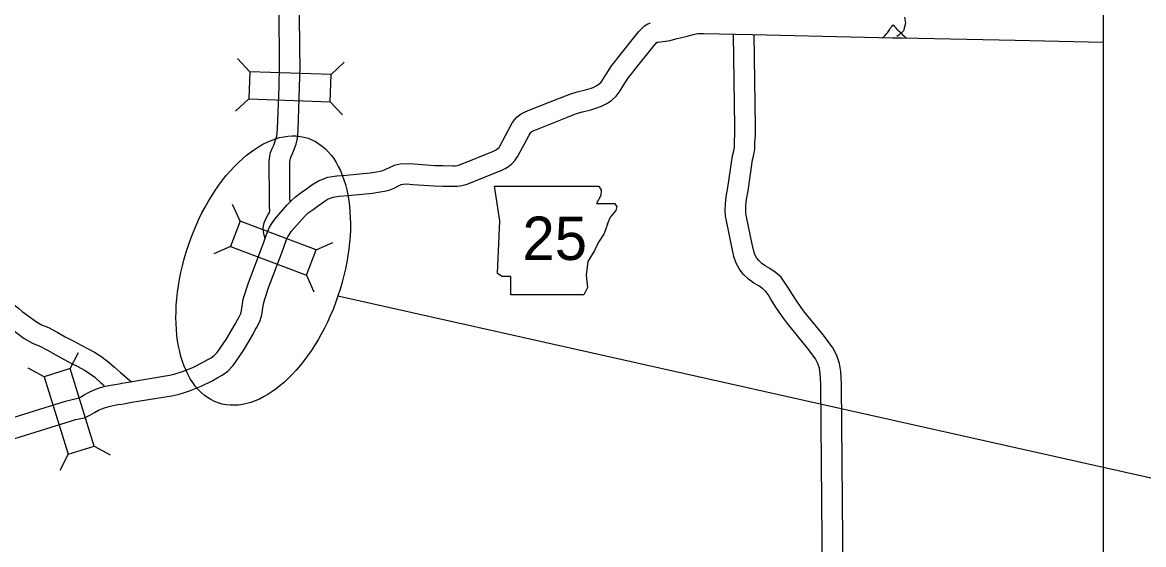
# Model space of a CAD drawing. Extents: x 1212896 to 1368412, y 378476 to 478763.
# Drawn here: x 1230517 to 1246876, y 456675 to 464301 of the extents above; entities that cross this region are included whole.
import ezdxf

# ---------------------------------------------------------------- set-up
doc = ezdxf.new("R2010")
doc.units = 0
for name, color, linetype in [('1', 7, 'Continuous'), ('Level 10', 7, 'Continuous'), ('Level 20', 7, 'Continuous'), ('Level 21', 7, 'Continuous'), ('R_Draft', 7, 'Continuous')]:
    doc.layers.add(name, color=color, linetype=linetype)

msp = doc.modelspace()

# ---------------------------------------------------------------- linework, layer by layer
at = {"layer": '1'}
msp.add_line((1235121, 460306), (1248775, 457249), dxfattribs=at)
msp.add_lwpolyline([(1215273, 477661), (1246287, 477661), (1246287, 445613), (1215273, 445613)], close=True, dxfattribs=at)
at = {"layer": 'Level 10'}
for points in [[(1234061, 461147), (1234043, 461192), (1234033, 461240), (1234029, 461301), (1234044, 461374), (1234075, 461443), (1234103, 461496), (1234124, 461524), (1234126, 461548), (1234123, 461614), (1234124, 461675), (1234121, 461705), (1234120, 461767), (1234118, 462222), (1234119, 462281), (1234126, 462342), (1234139, 462402), (1234161, 462458), (1234184, 462510), (1234207, 462567), (1234221, 462608), (1234229, 462641), (1234236, 462684), (1234239, 462747), (1234261, 463359), (1234269, 463669), (1234267, 463884), (1234256, 464690)], [(1234425, 461688), (1234425, 461691), (1234421, 461725), (1234420, 461769), (1234418, 462221), (1234419, 462261), (1234422, 462292), (1234427, 462315), (1234439, 462344), (1234461, 462395), (1234487, 462460), (1234509, 462521), (1234524, 462584), (1234535, 462654), (1234539, 462733), (1234560, 463349), (1234569, 463667), (1234567, 463887), (1234559, 464463)], [(1230081, 458438), (1231146, 458769), (1231221, 458791), (1231283, 458804), (1231328, 458813), (1231363, 458830), (1231418, 458862), (1231489, 458903), (1231562, 458937), (1231625, 458960), (1231705, 458982), (1231777, 458999), (1231863, 459015), (1231926, 459024), (1231967, 459030), (1232031, 459043), (1232664, 459148), (1232729, 459163), (1232777, 459177), (1232853, 459203), (1232918, 459227), (1233001, 459262), (1233145, 459334), (1233224, 459377), (1233270, 459402), (1233317, 459435), (1233358, 459479), (1233489, 459671), (1233620, 459895), (1233654, 459958), (1233680, 460000), (1233703, 460048), (1233714, 460092), (1233740, 460257), (1233766, 460346), (1233788, 460412), (1233815, 460499), (1234026, 461053), (1234093, 461240), (1234124, 461312), (1234156, 461362), (1234199, 461428), (1234374, 461630), (1234436, 461697), (1234500, 461753), (1234586, 461815), (1234662, 461868), (1234740, 461927), (1234835, 461989), (1234975, 462039), (1235104, 462059), (1235241, 462072), (1235589, 462105), (1235684, 462120), (1235735, 462130), (1235778, 462140), (1235820, 462156), (1235873, 462184), (1235944, 462215), (1236027, 462237), (1236121, 462242), (1236235, 462234), (1236537, 462213), (1236657, 462211), (1236794, 462207), (1236832, 462208), (1236867, 462213), (1236911, 462225), (1237393, 462420), (1237420, 462433), (1237436, 462443), (1237454, 462457), (1237471, 462475), (1237489, 462502), (1237645, 462794), (1237669, 462840), (1237701, 462883), (1237737, 462923), (1237793, 462963), (1237854, 462994), (1237922, 463022), (1238355, 463193), (1238441, 463230), (1238504, 463254), (1238613, 463286), (1238734, 463314), (1238802, 463335), (1238846, 463351), (1238889, 463373), (1238929, 463401), (1238960, 463426), (1238988, 463467), (1239031, 463533), (1239114, 463667), (1239159, 463725), (1239206, 463782), (1239510, 464166), (1239555, 464210), (1239594, 464251), (1239642, 464280), (1239680, 464296)], [(1243389, 464377), (1243402, 464289), (1243372, 464179), (1243311, 464117), (1243276, 464095)], [(1239758, 464008), (1239792, 464013), (1239968, 464038), (1240016, 464052), (1240072, 464067), (1240201, 464097), (1240306, 464122), (1240373, 464137), (1240456, 464137), (1240919, 464130), (1241172, 464125), (1243211, 464077), (1243354, 464076), (1245001, 464039), (1246287, 464010)], [(1242193, 456181), (1242168, 459007), (1242163, 459106), (1242159, 459169), (1242146, 459251), (1242124, 459317), (1242087, 459389), (1242034, 459461), (1241971, 459545), (1241679, 459905), (1241623, 459980), (1241566, 460065), (1241503, 460159), (1241438, 460259), (1241398, 460328), (1241365, 460373), (1241319, 460412), (1241261, 460452), (1241189, 460493), (1241110, 460551), (1241034, 460625), (1240982, 460697), (1240931, 460784), (1240898, 460880), (1240871, 461000), (1240790, 461403), (1240776, 461473), (1240773, 461558), (1240776, 461646), (1240786, 461755), (1240811, 461892), (1240877, 462351), (1240897, 462425), (1240905, 462479), (1240906, 462564), (1240913, 462663), (1240914, 462776), (1240894, 464126), (1240891, 464128)], [(1243067, 464078), (1243075, 464083), (1243087, 464092), (1243095, 464101), (1243104, 464109), (1243116, 464122), (1243131, 464138), (1243138, 464149), (1243151, 464164), (1243160, 464179), (1243168, 464190), (1243176, 464202), (1243186, 464220), (1243194, 464232), (1243201, 464240), (1243214, 464253), (1243223, 464263), (1243231, 464255), (1243244, 464243), (1243256, 464224), (1243270, 464209), (1243284, 464195), (1243293, 464185), (1243313, 464168), (1243334, 464148), (1243343, 464138), (1243359, 464119), (1243381, 464101), (1243396, 464091), (1243414, 464074)], [(1230170, 458151), (1231233, 458482), (1231293, 458500), (1231344, 458510), (1231423, 458527), (1231502, 458564), (1231568, 458603), (1231627, 458636), (1231677, 458659), (1231716, 458674), (1231781, 458692), (1231839, 458706), (1231911, 458719), (1231968, 458727), (1232019, 458734), (1232086, 458748), (1232723, 458854), (1232804, 458873), (1232867, 458890), (1232954, 458921), (1233028, 458947), (1233127, 458989), (1233284, 459068), (1233368, 459114), (1233430, 459148), (1233515, 459208), (1233592, 459290), (1233743, 459511), (1233882, 459748), (1233915, 459809), (1233944, 459857), (1233986, 459945), (1234008, 460030), (1234033, 460191), (1234053, 460257), (1234073, 460319), (1234099, 460400), (1234307, 460948), (1234372, 461130), (1234390, 461171), (1234408, 461199), (1234440, 461247), (1234598, 461429), (1234646, 461482), (1234688, 461518), (1234759, 461570), (1234839, 461625), (1234913, 461682), (1234970, 461719), (1235049, 461747), (1235141, 461761), (1235270, 461774), (1235626, 461807), (1235737, 461824), (1235798, 461837), (1235866, 461852), (1235943, 461882), (1236004, 461913), (1236043, 461931), (1236074, 461939), (1236119, 461941), (1236214, 461935), (1236523, 461913), (1236649, 461911), (1236794, 461907), (1236860, 461908), (1236929, 461920), (1237005, 461940), (1237512, 462145), (1237563, 462168), (1237608, 462197), (1237659, 462236), (1237706, 462288), (1237745, 462345), (1237910, 462653), (1237924, 462679), (1237934, 462693), (1237939, 462698), (1237950, 462706), (1237979, 462721), (1238033, 462743), (1238470, 462916), (1238553, 462951), (1238600, 462969), (1238689, 462996), (1238812, 463024), (1238899, 463051), (1238968, 463076), (1239043, 463115), (1239111, 463161), (1239183, 463222), (1239237, 463300), (1239285, 463373), (1239360, 463496), (1239393, 463537), (1239440, 463594), (1239734, 463965), (1239769, 464000), (1239782, 464014), (1239793, 464018)], [(1242493, 456183), (1242467, 459015), (1242462, 459122), (1242458, 459201), (1242439, 459321), (1242402, 459435), (1242342, 459547), (1242276, 459640), (1242206, 459731), (1241916, 460088), (1241869, 460152), (1241816, 460232), (1241754, 460325), (1241693, 460418), (1241649, 460491), (1241588, 460578), (1241501, 460651), (1241421, 460706), (1241354, 460744), (1241304, 460781), (1241262, 460822), (1241234, 460860), (1241205, 460909), (1241188, 460962), (1241165, 461063), (1241084, 461461), (1241075, 461509), (1241073, 461559), (1241075, 461626), (1241083, 461714), (1241107, 461843), (1241172, 462292), (1241191, 462365), (1241204, 462454), (1241206, 462551), (1241213, 462651), (1241214, 462777), (1241194, 464123)], [(1230174, 460405), (1230378, 460193), (1230459, 460126), (1230515, 460079), (1230616, 460004), (1230707, 459938), (1230797, 459886), (1230897, 459843), (1231025, 459779), (1231141, 459711), (1231266, 459645), (1231375, 459586), (1231466, 459539), (1231569, 459483), (1231661, 459428), (1231764, 459349), (1231860, 459264), (1231950, 459186), (1232081, 459074), (1232109, 459050)], [(1229958, 460197), (1230174, 459973), (1230266, 459896), (1230328, 459843), (1230439, 459761), (1230544, 459686), (1230662, 459618), (1230770, 459571), (1230882, 459515), (1230995, 459449), (1231124, 459380), (1231235, 459321), (1231326, 459274), (1231421, 459222), (1231492, 459180), (1231572, 459118), (1231663, 459038), (1231708, 458999)]]:
    msp.add_lwpolyline(points, dxfattribs=at)
at = {"layer": 'Level 20'}
for p, q in [((1233833, 463579), (1233653, 463772)), ((1235020, 463538), (1235213, 463718)), ((1233833, 463579), (1233819, 463184)), ((1235020, 463538), (1233833, 463579)), ((1235007, 463142), (1235020, 463538)), ((1233819, 463184), (1233626, 463003)), ((1233819, 463184), (1235007, 463142)), ((1235007, 463142), (1235187, 462949)), ((1233692, 461400), (1233584, 461640)), ((1233692, 461400), (1233552, 461029)), ((1234803, 460978), (1233692, 461400)), ((1233552, 461029), (1233311, 460921)), ((1233552, 461029), (1234662, 460608)), ((1234803, 460978), (1235044, 461086)), ((1234662, 460608), (1234803, 460978)), ((1234662, 460608), (1234771, 460367)), ((1231212, 459245), (1231334, 459479)), ((1230834, 459127), (1230600, 459250)), ((1231212, 459245), (1230834, 459127)), ((1231564, 458111), (1231212, 459245)), ((1230834, 459127), (1231186, 457993)), ((1231186, 457993), (1231564, 458111)), ((1231564, 458111), (1231798, 457988)), ((1231186, 457993), (1231064, 457759))]:
    msp.add_line(p, q, dxfattribs=at)
at = {"layer": 'Level 21'}
for p, q in [((1237483, 461403), (1237407, 461910)), ((1237407, 461910), (1238928, 461909)), ((1238928, 461909), (1238963, 461851)), ((1238929, 461910), (1238929, 461910)), ((1238963, 461851), (1238955, 461775)), ((1238955, 461775), (1238896, 461656)), ((1238896, 461656), (1239158, 461656)), ((1239175, 461555), (1239099, 461462)), ((1239158, 461656), (1239192, 461614)), ((1239192, 461614), (1239175, 461555)), ((1237449, 460633), (1237483, 461403)), ((1239056, 461352), (1239005, 461217)), ((1239056, 461352), (1239099, 461462)), ((1239005, 461217), (1238921, 461090)), ((1238921, 461090), (1238862, 460971)), ((1238862, 460971), (1238769, 460811)), ((1238769, 460811), (1238743, 460608)), ((1237517, 460591), (1237449, 460633)), ((1237644, 460591), (1237517, 460591)), ((1237644, 460320), (1237644, 460591)), ((1238743, 460608), (1238760, 460430)), ((1238760, 460430), (1238709, 460320)), ((1238709, 460320), (1237644, 460320))]:
    msp.add_line(p, q, dxfattribs=at)
at = {"layer": 'R_Draft'}
msp.add_ellipse((1234030, 460676), major_axis=(-655, -1932), ratio=0.564938, dxfattribs=at)

# ---------------------------------------------------------------- texts
at = {"layer": 'Level 21'}
msp.add_text('25', height=633.6, dxfattribs=at).set_placement((1237813, 460831))

doc.saveas('drawing.dxf')
